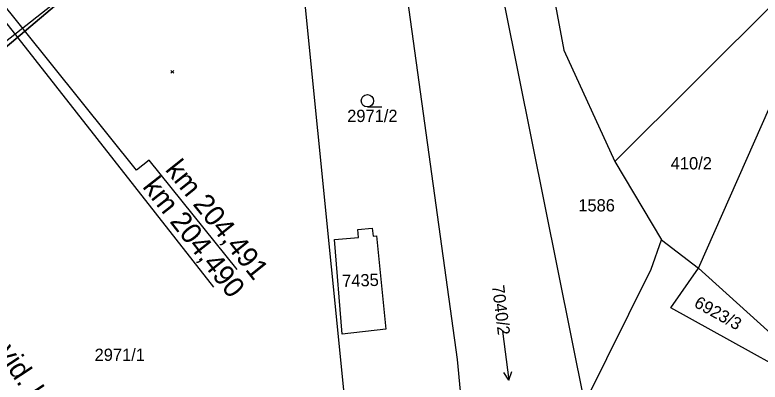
# Model space of a CAD drawing. Extents: x -800194 to -799078, y -1007177 to -1006597.
# Drawn here: x -799466.4 to -799375.6, y -1006986.1 to -1006941.3 of the extents above; entities that cross this region are included whole.
import ezdxf

# ---------------------------------------------------------------- set-up
doc = ezdxf.new("R2010")
doc.units = 0
for name, color, linetype in [('Vrstva 18', 7, 'Continuous'), ('Vrstva 3', 7, 'Continuous'), ('Vrstva 49', 7, 'Continuous'), ('Vrstva 53', 7, 'Continuous'), ('Vrstva 55', 7, 'Continuous'), ('Vrstva 57', 7, 'Continuous'), ('Vrstva 58', 7, 'Continuous')]:
    doc.layers.add(name, color=color, linetype=linetype)

msp = doc.modelspace()

# ---------------------------------------------------------------- linework, layer by layer
at = {"layer": 'Vrstva 3'}
msp.add_line((-799442.19, -1006974.528), (-799473.063, -1006935.201), dxfattribs=at)
msp.add_lwpolyline([(-799439.356, -1006972.379), (-799450.062, -1006959.03), (-799451.608, -1006960.27), (-799472.235, -1006934.552)], dxfattribs=at)
at = {"layer": 'Vrstva 49'}
for p, q in [((-799447.445, -1006948.079), (-799447.091, -1006948.433)), ((-799447.445, -1006948.433), (-799447.091, -1006948.079))]:
    msp.add_line(p, q, dxfattribs=at)
msp.add_lwpolyline([(-799423.903, -1006906.911), (-799427.313, -1006910.033), (-799439.866, -1006919.177), (-799453.667, -1006933.596), (-799478.523, -1006953.199), (-799482.72, -1006952.931), (-799486.865, -1006949.018)], dxfattribs=at)
at = {"layer": 'Vrstva 53'}
msp.add_lwpolyline([(-799312.398, -1006791.976), (-799331.37, -1006811.87), (-799413.75, -1006898.23), (-799418.41, -1006902.53), (-799423.07, -1006906.83), (-799433.4, -1006916.39), (-799469.5, -1006946.86), (-799487.22, -1006958.47), (-799495.25, -1006963.74), (-799521.98, -1006977.8), (-799546.71, -1006987.83)], dxfattribs=at)
at = {"layer": 'Vrstva 55'}
for p, q in [((-799424.1, -1007009.73), (-799433.4, -1006916.39)), ((-799393.3, -1006959.22), (-799364.81, -1006930.69)), ((-799383.1, -1006972.22), (-799364.81, -1006930.69)), ((-799393.3, -1006959.22), (-799387.62, -1006968.78)), ((-799387.62, -1006968.78), (-799383.1, -1006972.22)), ((-799364.19, -1006989.42), (-799383.1, -1006972.22))]:
    msp.add_line(p, q, dxfattribs=at)
for points in [[(-799413.75, -1006898.23), (-799411.99, -1006904.75), (-799406.72, -1006940.36), (-799397.01, -1006988.73)], [(-799407.32, -1006903.81), (-799399.52, -1006945.6), (-799393.3, -1006959.22)], [(-799410.89, -1007000.14), (-799412.5, -1006983.38), (-799423.07, -1006906.83)], [(-799487.22, -1006958.47), (-799469.5, -1006946.86), (-799433.4, -1006916.39)], [(-799422.35, -1006968.27), (-799421.24, -1006979.68), (-799426.55, -1006980.27), (-799427.48, -1006968.72), (-799424.58, -1006968.47), (-799424.66, -1006967.5), (-799422.89, -1006967.35), (-799422.79, -1006968.31), (-799422.35, -1006968.27)], [(-799397.01, -1006988.73), (-799388.9, -1006972.36), (-799387.62, -1006968.78)], [(-799364.19, -1006989.42), (-799386.5, -1006977.04), (-799383.1, -1006972.22)]]:
    msp.add_lwpolyline(points, dxfattribs=at)
at = {"layer": 'Vrstva 58'}
for p, q in [((-799423.483, -1006952.54), (-799421.733, -1006952.54)), ((-799407.012, -1006979.92), (-799406.225, -1006985.869)), ((-799406.225, -1006985.869), (-799406.851, -1006984.965)), ((-799406.225, -1006985.869), (-799405.856, -1006984.834))]:
    msp.add_line(p, q, dxfattribs=at)
msp.add_circle((-799423.483, -1006951.79), 0.75, dxfattribs=at)

# ---------------------------------------------------------------- texts
at = {"layer": 'Vrstva 18'}
for s, height, p in [('sv.kol.3,80m vol.v.5,00m', 1.5, (-799474.767, -1006978.685)), ('evid. km 204,470', 2.5, (-799469.707, -1006980.948))]:
    msp.add_text(s, height=height, rotation=303.35536, dxfattribs=at).set_placement(p)
at = {"layer": 'Vrstva 3'}
for s, rotation, p in [('km 204,491', 308.73131, (-799448.213, -1006960.224)), ('km 204,490', 308.13277, (-799450.981, -1006962.309))]:
    msp.add_text(s, height=2.5, rotation=rotation, dxfattribs=at).set_placement(p)
at = {"layer": 'Vrstva 57'}
for s, p in [('2971/2', (-799425.94, -1006954.386)), ('410/2', (-799386.5, -1006960.17)), ('1586', (-799397.769, -1006965.3)), ('2971/1', (-799456.73, -1006983.54))]:
    msp.add_text(s, height=1.5, dxfattribs=at).set_placement(p)
for s, rotation, p in [('7435', 2, (-799426.526, -1006974.533)), ('7040/2', 277, (-799408.301, -1006974.367)), ('6923/3', 331, (-799383.769, -1006976.865))]:
    msp.add_text(s, height=1.5, rotation=rotation, dxfattribs=at).set_placement(p)

doc.saveas('drawing.dxf')
